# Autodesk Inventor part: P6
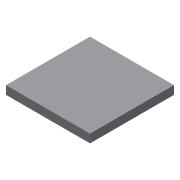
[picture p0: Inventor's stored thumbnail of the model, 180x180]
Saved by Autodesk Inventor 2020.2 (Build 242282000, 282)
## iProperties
Created: 2005-11
Part Number: P6
Document SubType Name: Modeling
Designer: F.Stasiak
Density: 1 g/cm^3
Material: Ogólny
Appearance: Domyślna
Manager: www.cadconsulting.pl
Company: Fabian Stasiak CAD Consulting
Author: F.Stasiak
Subject: Zbiór ćwiczeń. Autodesk Inventor 2020. Kurs podstawowy
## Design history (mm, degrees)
sketch "Szkic1"
  geometry: L1 (50, 50)-(50, -50); L2 (50, -50)-(-50, -50); L3 (-50, -50)-(-50, 50); L4 (-50, 50)-(50, 50); 2 further points
  constraints: 8 end point, 1 coincident, 7 other
  dimensions: "d0" = 100 distance of L1.end L2.end
extrude "Wyciągnięcie proste1" new body sketch "Szkic1" distance "d1" = 10; taper "d2" = 0 deg
node "Bryła1"
node "Korpusy bryłowe"
node "Korpusy powierzchniowe"
